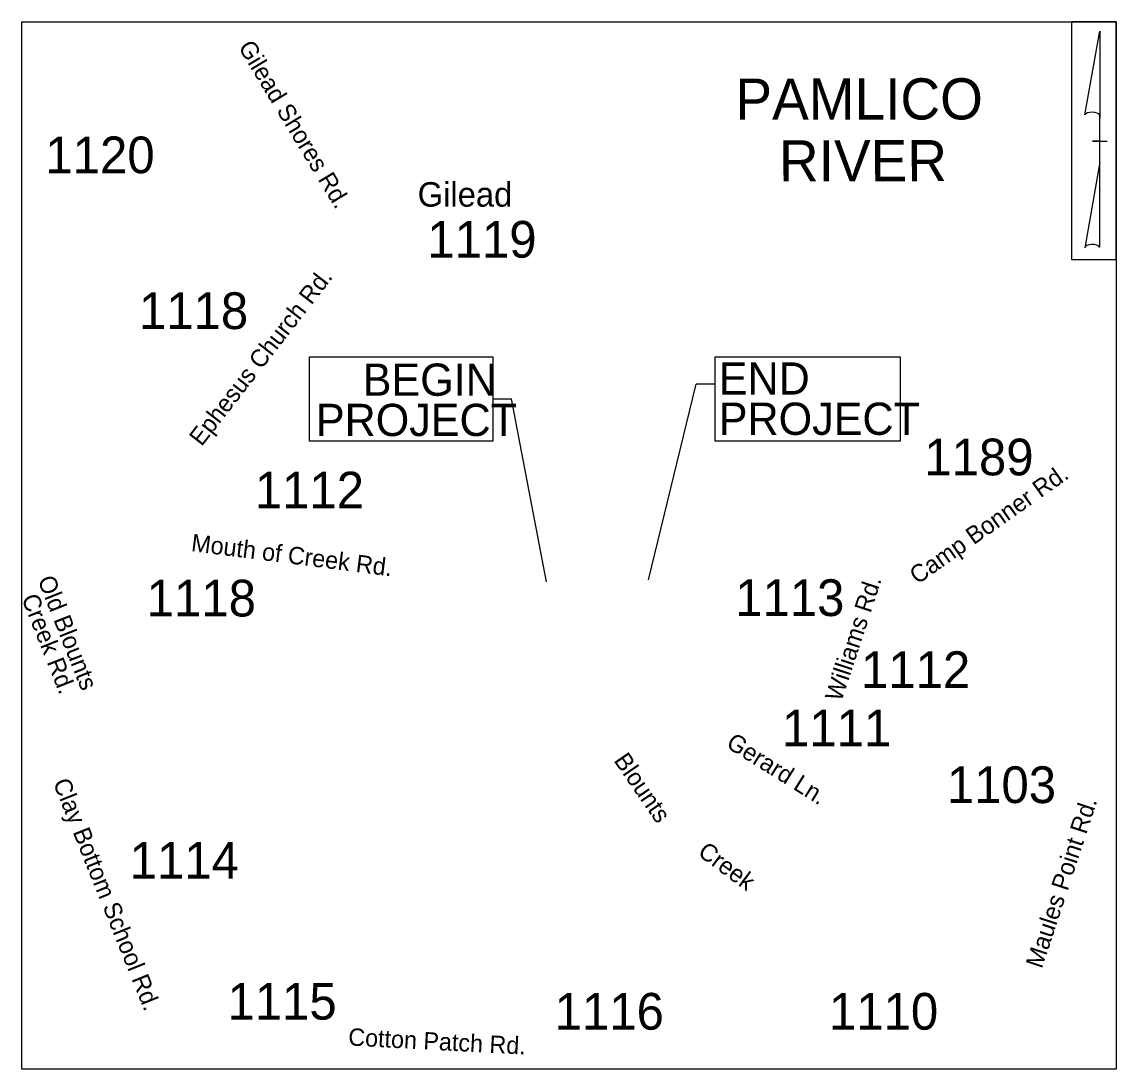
# Model space of a CAD drawing. Extents: x 2436891 to 2615003, y 608482 to 790044.
# Drawn here: x 2592651 to 2615003, y 608482 to 629869 of the extents above; entities that cross this region are included whole.
import ezdxf

# ---------------------------------------------------------------- set-up
doc = ezdxf.new("R2010")
doc.units = 0
for name, color, linetype in [('Default', 7, 'Continuous'), ('Old_Level_9', 7, 'Continuous'), ('Prop North Arrow for Plan Sheets CELL', 7, 'Continuous'), ('Sheet Block Title CELL', 7, 'Continuous')]:
    doc.layers.add(name, color=color, linetype=linetype)

msp = doc.modelspace()

# ---------------------------------------------------------------- linework, layer by layer
at = {"layer": 'Old_Level_9'}
for p, q in [((2605453, 618475), (2606427, 622469)), ((2606814, 622469), (2606427, 622469)), ((2602269, 622169), (2602656, 622169)), ((2603369, 618431), (2602656, 622169))]:
    msp.add_line(p, q, dxfattribs=at)
for points in [[(2598529, 623031), (2602269, 623031), (2602269, 621306), (2598529, 621306)], [(2606814, 623031), (2610589, 623031), (2610589, 621307), (2606814, 621306)]]:
    msp.add_lwpolyline(points, close=True, dxfattribs=at)
at = {"layer": 'Prop North Arrow for Plan Sheets CELL'}
for p, q in [((2614365, 627971), (2614668, 629682)), ((2614669, 629682), (2614668, 629682)), ((2614669, 629682), (2614668, 629682)), ((2614669, 629682), (2614669, 627917)), ((2614669, 627002), (2614669, 627969)), ((2614669, 627917), (2614669, 627967)), ((2614522, 627430), (2614520, 627430)), ((2614653, 627430), (2614522, 627430)), ((2614524, 627430), (2614819, 627430)), ((2614669, 627002), (2614361, 625257)), ((2614671, 625265), (2614669, 627002))]:
    msp.add_line(p, q, dxfattribs=at)
for centre, start_param, end_param in [((2614518, 627952), 0.216388, 2.908219), ((2614518, 625251), 0.201328, 3.141593)]:
    msp.add_ellipse(centre, major_axis=(156, -1), ratio=0.461098, start_param=start_param, end_param=end_param, dxfattribs=at)
at = {"layer": 'Sheet Block Title CELL'}
for points in [[(2592651, 629869), (2615003, 629869), (2615003, 608482), (2592651, 608482)], [(2615003, 629869), (2614089, 629869), (2614089, 625016), (2615003, 625016)]]:
    msp.add_lwpolyline(points, close=True, dxfattribs=at)

# ---------------------------------------------------------------- texts
at = {"layer": 'Default'}
for s, height, rotation, p in [('Gilead Shores Rd.', 356.25, 301.1067, (2597062, 629355)), ('PAMLICO', 840, 0.077, (2607227, 627871)), ('RIVER', 840, 0.077, (2608117, 626612)), ('Ephesus Church Rd.', 356.25, 52.1939, (2596323, 621185)), ('Camp Bonner Rd.', 356.25, 35.1162, (2610945, 618371)), ('Mouth of Creek Rd.', 356.25, 352.8113, (2596097, 619062)), ('Old Blounts', 356.25, 291.6032, (2592969, 618477)), ('Williams Rd.', 356.25, 71.7679, (2609390, 615971)), ('Creek Rd.', 356.2, 291.6032, (2592639, 618102)), ('Gerard Ln.', 356.2, 327.9874, (2607016, 615069)), ('Blounts', 356.2, 304.5539, (2604730, 614785)), ('Clay Bottom School Rd.', 356.25, 291.8478, (2593281, 614335)), ('Maules Point Rd.', 356.25, 71.7679, (2613487, 610519)), ('Creek', 356.2, 323.4553, (2606437, 612863)), ('Cotton Patch Rd.', 356.25, 357.0368, (2599312, 608965))]:
    msp.add_text(s, height=height, rotation=rotation, dxfattribs=at).set_placement(p)
for s, height, p in [('1120', 750, (2593132, 626778)), ('Gilead', 500, (2600736, 626096)), ('1119', 750, (2600934, 625054)), ('1118', 750, (2595043, 623596)), ('1189', 750, (2611086, 620608)), ('1112', 750, (2597409, 619932)), ('1118', 750, (2595202, 617726)), ('1113', 750, (2607222, 617735)), ('1112', 750, (2609792, 616264)), ('1111', 750, (2608180, 615074)), ('1103', 750, (2611546, 613915)), ('1114', 750, (2594854, 612370)), ('1115', 750, (2596851, 609492)), ('1116', 750, (2603535, 609287)), ('1110', 750, (2609138, 609287))]:
    msp.add_text(s, height=height, dxfattribs=at).set_placement(p)
at = {"layer": 'Old_Level_9'}
for s, p in [('BEGIN', (2599614, 622233)), ('END', (2606887, 622258)), ('PROJECT', (2598657, 621411)), ('PROJECT', (2606887, 621435))]:
    msp.add_text(s, height=658.2, rotation=360, dxfattribs=at).set_placement(p)

doc.saveas('drawing.dxf')
